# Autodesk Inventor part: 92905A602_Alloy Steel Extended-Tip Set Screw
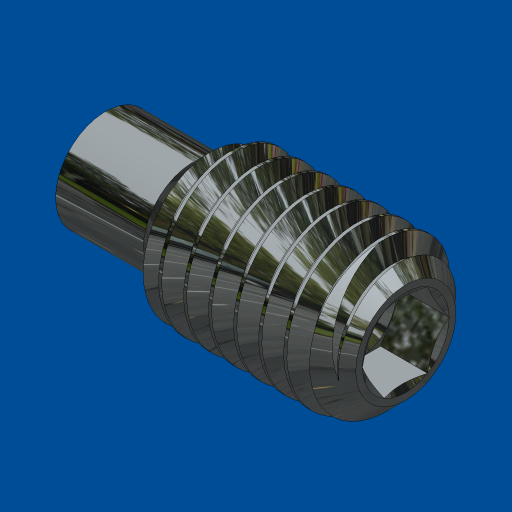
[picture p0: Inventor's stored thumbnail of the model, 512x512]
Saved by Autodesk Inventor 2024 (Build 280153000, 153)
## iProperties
Created: 2022-03
Part Number: 92905A602_Alloy Steel Extended-Tip Set Screw
Material: Steel
Description: STEP AP203
Document SubType Name: Modeling
Designer: amoles
Appearance: Zinc
Mass: 0.207975 g
Surface Area: 0.820327 cm^2
Volume: 0.0264937 cm^3
Density: 7.85 g/cm^3
Company: Managed by Terraform
Sending System: SolidWorks 2017
Preprocessor: SwSTEP 2.0
Title: 92905A602_Alloy Steel Extended-Tip Set Screw.STEP
Author: Administrator
Revision Number: ANY
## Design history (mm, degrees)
feature "Cut-Sweep1"
body "Solid1"
